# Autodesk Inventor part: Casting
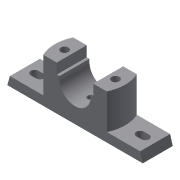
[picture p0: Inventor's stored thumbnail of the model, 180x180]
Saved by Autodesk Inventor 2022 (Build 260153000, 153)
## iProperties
Created: 2009-04
Part Number: Casting
Document SubType Name: Modeling
Designer: Sham
Density: 1 g/cm^3
Material: Generic
Appearance: Default
Author: Sham
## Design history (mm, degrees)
sketch "Sketch1"
  geometry: L1 (-104, 0)-(104, 0); L2 (-104, 0)-(-100, 14); L3 (-100, 14)-(100, 14); L4 (100, 14)-(104, 0); 1 further point
  constraints: 8 end point, 1 horizontal, 1 midpoint, 1 parallel, 1 other
  dimensions: "d0" = 208 distance of L1.start L1.end; "d1" = 104 distance of L1.end point (0, 0); "d2" = 4 horizontal distance of L1.start L2.end; "d3" = 4 horizontal distance of L1.end L3.end; "d10" = 14 distance between parallel lines of L1 L3
extrude "Extrusion1" new body sketch "Sketch1" stored distance "d4" = 46; taper "d5" = 0 deg
sketch "Sketch2"
  geometry: L1 (51.143, 46)-(148.857, 46); L2 (148.857, 0)-(51.143, 0); A1 r 54 centre (100, 23) between (51.143, 46) and (51.143, 0); A2 r 54 centre (100, 23) between (148.857, 0) and (148.857, 46)
  constraints: 4 end point, 4 point on circle, 2 centre point, 1 parallel
extrude "Extrusion2" join sketch "Sketch2" distance "d8" = 54; taper "d9" = 0 deg
sketch "Sketch3"
  geometry: L1 (-28, 68)-(-28, 52); L2 (-28, 52)-(-24, 52); L3 (28, 68)-(28, 52); L4 (28, 52)-(24, 52); L5 (-28, 68)-(28, 68); L6 (-100, 14)-(-48.857, 14) reference; L7 (0, 48)-(0, 19); L8 (48.857, 14)-(100, 14) reference; L9 (48.857, 68)-(-48.857, 68) reference; L10 (-24, 48)-(-24, 52); L11 (24, 48)-(24, 52); A1 r 24 centre (0, 48) between (-24, 48) and (24, 48); 1 further point
  constraints: 16 end point, 5 perpendicular, 2 point on circle, 2 symmetric about line, 1 centre point, 1 tangent, 1 vertical alignment, 1 other
  dimensions: "d11" = 16 distance of L1.start L1.end; "d16" = 24 radius of A1; "d17" = 16 distance of L3.start L3.end; "d52" = 56 distance between parallel lines of L1 L3; "d54" = 54 distance between parallel lines of L8 L9 (derived)
extrude "Extrusion3" cut sketch "Sketch3" distance "d18" = 54; taper "d19" = 0 deg
sketch "Sketch4"
  geometry: L1 (-23, 29)-(-15, 29); L2 (-15, 17)-(-23, 17); L3 (-185, 29)-(-177, 29); L4 (-177, 17)-(-185, 17); A1 r 6 centre (-15, 23) between (-15, 17) and (-15, 29); A2 r 6 centre (-23, 23) between (-23, 29) and (-23, 17); A3 r 6 centre (-177, 23) between (-177, 17) and (-177, 29); A4 r 6 centre (-185, 23) between (-185, 29) and (-185, 17)
  constraints: 8 end point, 8 point on circle, 8 tangent, 4 centre point, 3 parallel
  dimensions: "d20" = 8 distance of A1.centre A2.centre; "d21" = 6 radius of A1; "d24" = 6 radius of A3; "d25" = 8 distance of A4.centre A3.centre
extrude "Extrusion4" cut sketch "Sketch4" distance "d28" = 54; taper "d29" = 0 deg
sketch "Sketch5"
  geometry: L1 (208, 0)-(0, 0) reference; L2 (52, -10)-(78, -10); L3 (78, -10)-(78, -36); L4 (78, -36)-(52, -36); L5 (52, -36)-(52, -10); L6 (130, -10)-(156, -10); L7 (156, -10)-(156, -36); L8 (156, -36)-(130, -36); L9 (130, -36)-(130, -10); L10 (0, -46)-(208, -46) reference; L11 (104, -23)-(104, -46)
  constraints: 18 end point, 5 perpendicular, 4 parallel, 2 horizontal, 1 midpoint
  dimensions: "d30" = 26 distance of L2.start L2.end; "d31" = 10 distance between parallel lines of L2 L1; "d32" = 10 distance between parallel lines of L1 L6; "d65" = 26 distance between parallel lines of L3 L11; "d66" = 26 distance between parallel lines of L9 L11
extrude "Extrusion5" cut sketch "Sketch5" distance "d34" = 10; taper "d35" = 0 deg
sketch "Sketch6"
  geometry: L1 (148.857, 0)-(128, 0) reference; L2 (72, 0)-(51.143, 0) reference; L3 (0, 46)-(0, 0) reference; L4 (200, 46)-(200, 0) reference; C1 r 6 at (61, 23); C2 r 6 at (139, 23); 1 further point
  constraints: 2 centre point, 1 equal radius
  dimensions: "d36" = 12 diameter of C1; "d37" = 78 distance of C2.centre C1.centre; "d39" = 39 distance of C2.centre point (100, 23); "d58" = 39 distance of C1.centre point (100, 23); "d59" = 23 distance from line of L1 C2.centre; "d60" = 23 distance from line of L2 C1.centre; "d61" = 61 distance from line of L3 C1.centre; "d62" = 61 distance from line of L4 C2.centre (derived)
extrude "Extrusion6" cut sketch "Sketch6" extent not by distance; stored distance "d40" = 10; taper "d41" = 0 deg
workplane "Work Plane1"
sketch "Sketch7"
  geometry: L1 (-4, 46)-(204, 46) reference; L2 (-4, 0)-(-4, 46) reference; 1 further point
  dimensions: "d43" = 23 distance from line of L1 point (100, 23); "d44" = 104 distance from line of point (100, 23) L2
hole "Hole1" sketch "Sketch7" at (100, 23) diameter "d45" = 8; stored, may be unused: countersink angle "d49" = 90 deg, drill point angle "d51" = 118 deg; dims "d46" = 6, "d47" = 8, "d48" = 16, "d50" = 8
body "Solid1"
other parameters: "d6" = 108, "d42" = -52
